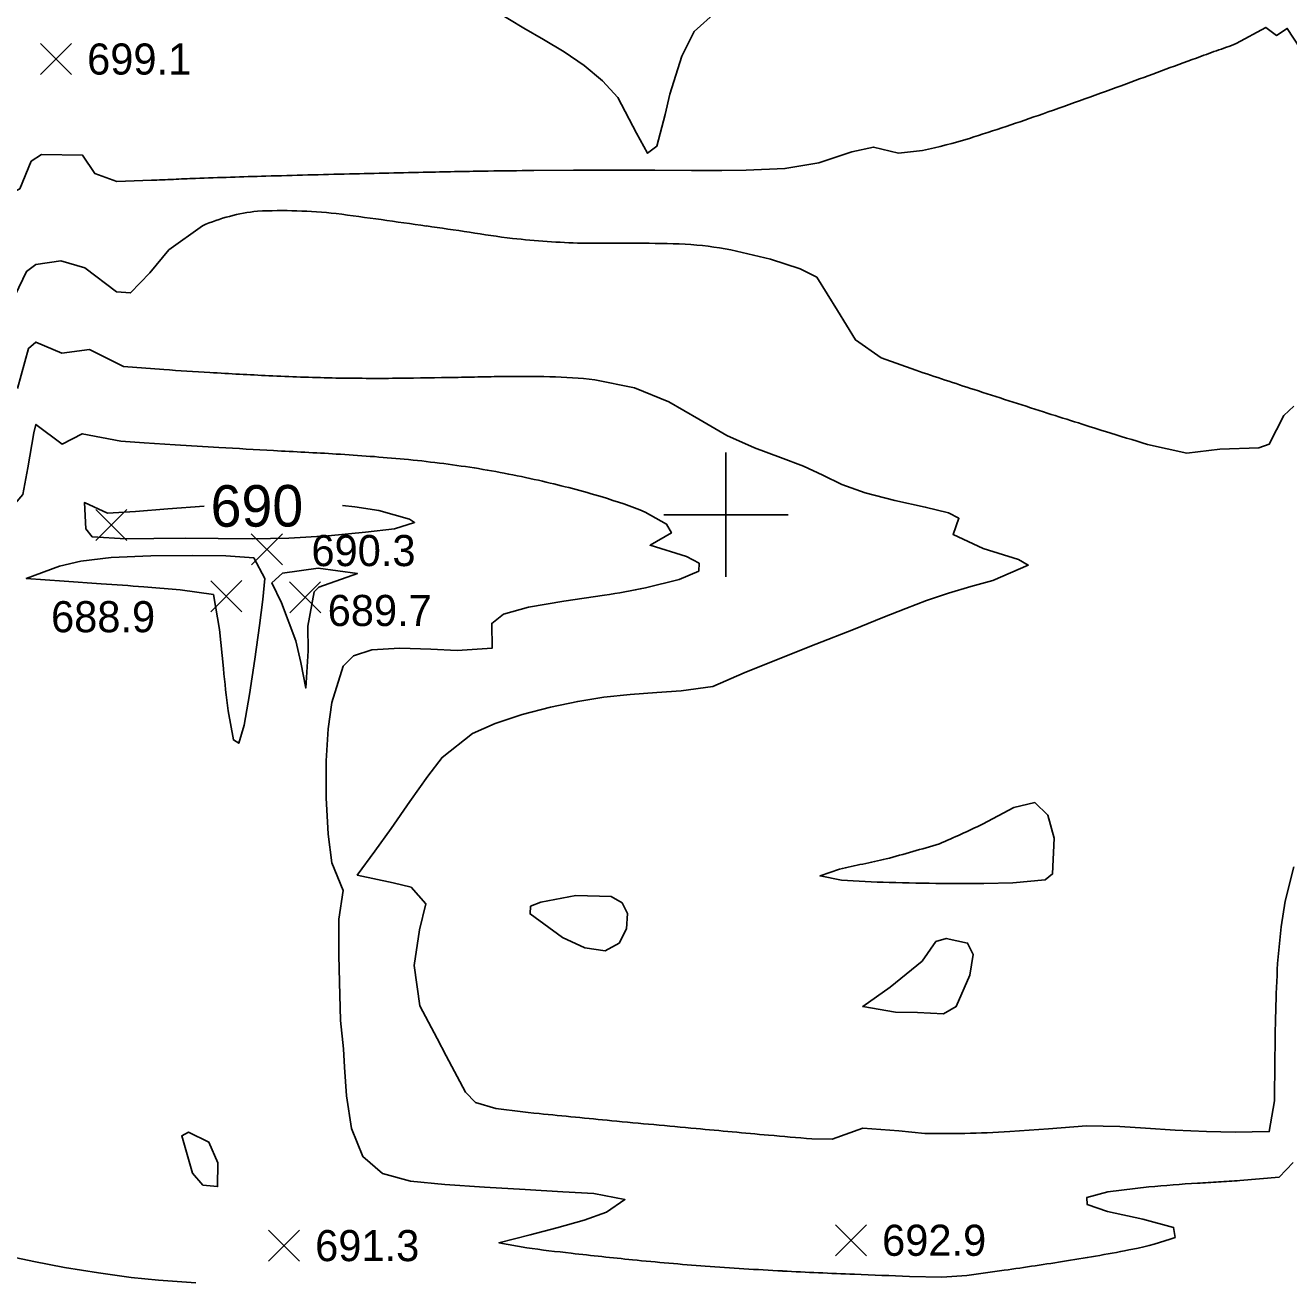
# Model space of a CAD drawing. Extents: x 2566079 to 2571326, y 424054 to 426896.
# Drawn here: x 2566662 to 2567271, y 425631 to 426236 of the extents above; entities that cross this region are included whole.
import ezdxf

# ---------------------------------------------------------------- set-up
doc = ezdxf.new("R2010")
doc.units = 0
for name, color, linetype in [('Contour_ADS_Label_Major', 7, 'Continuous'), ('Contour_ADS_Major', 7, 'Continuous'), ('Contour_ADS_Minor', 7, 'Continuous'), ('Contour_ADS_Spot_Elevation', 7, 'Continuous'), ('Contour_ADS_Tick', 7, 'Continuous')]:
    doc.layers.add(name, color=color, linetype=linetype)

# ---------------------------------------------------------------- blocks, each defined once
blk = doc.blocks.new('S890')
at = {"layer": 'Contour_ADS_Tick'}
for p, q in [((0, -0.5), (0, 0.5)), ((-0.5, 0), (0.5, 0))]:
    blk.add_line(p, q, dxfattribs=at)
blk = doc.blocks.new('S750')
at = {"layer": 'Contour_ADS_Spot_Elevation'}
for p, q in [((-0.5, 0.498), (0.5, -0.498)), ((-0.498, -0.5), (0.498, 0.5))]:
    blk.add_line(p, q, dxfattribs=at)

msp = doc.modelspace()

# ---------------------------------------------------------------- linework, layer by layer
at = {"layer": 'Contour_ADS_Major'}
for points in [[(2566888.81, 426242.96), (2566902.59, 426234.55), (2566911.98, 426229.21), (2566921.97, 426223.21), (2566931.71, 426216.58), (2566940.54, 426209.24), (2566947.81, 426201.1), (2566956.85, 426183.98), (2566962.22, 426174.26), (2566966.65, 426177.67), (2566970.7, 426193), (2566973.03, 426202.77), (2566978.76, 426221.15), (2566984.63, 426233), (2566995.41, 426242.7)], [(2566815.11, 426004.41), (2566821.12, 426003.85), (2566832.73, 426001.97), (2566847.42, 425997.84), (2566849.9, 425996.21), (2566840.22, 425993.27), (2566826.27, 425991.54), (2566808.31, 425989.89), (2566789.3, 425988.76), (2566771.62, 425988.44), (2566755.23, 425988.61), (2566739.52, 425988.77), (2566724.24, 425988.59), (2566710.64, 425988.37), (2566694.44, 425989.4), (2566691.4, 425993.17), (2566690.77, 426005.9), (2566701.93, 426000.74), (2566715.39, 426001.5), (2566730.94, 426002.84), (2566748.45, 426004.19)], [(2566698.75, 425966.73), (2566680.91, 425967.98), (2566662.72, 425969.27), (2566678.81, 425975.27), (2566689.01, 425977.58), (2566703.6, 425979.38), (2566722.68, 425980.24), (2566742.64, 425980.36), (2566758.95, 425980.15), (2566772.34, 425979.25), (2566777.69, 425969.22), (2566776.72, 425959.21), (2566775.07, 425946.63), (2566772.85, 425930.39), (2566770.33, 425913.33), (2566767.76, 425898.51), (2566765.18, 425889.83), (2566762.6, 425891.45), (2566760.04, 425905.46)], [(2566752.92, 425961.49), (2566736.86, 425963.87), (2566719.31, 425965.25)], [(2566757.72, 425925.87), (2566755.84, 425944.67), (2566752.92, 425961.49), (2566752.92, 425961.49)], [(2566550.65, 425693.94), (2566568.5, 425685.76), (2566581.26, 425680.38), (2566598.08, 425674.36), (2566609.39, 425672.46), (2566620.97, 425670.92), (2566634.05, 425668.83), (2566644.64, 425666.21), (2566649.77, 425663.14), (2566650.37, 425659.79), (2566638.84, 425647.23), (2566654.95, 425642.36), (2566666.37, 425639.9), (2566681.19, 425637.14), (2566697.58, 425634.46), (2566713.29, 425632.28), (2566726.44, 425630.92), (2566744.39, 425629.75)]]:
    msp.add_lwpolyline(points, dxfattribs=at)
msp.add_lwpolyline([(2566801.49, 425962.77), (2566798.51, 425946.32), (2566798.61, 425934.46), (2566797.48, 425916.45), (2566795.05, 425928.71), (2566792.68, 425939.17), (2566785.71, 425957.59), (2566781.15, 425967.13), (2566786.17, 425971.82), (2566803.41, 425974.3), (2566822.37, 425971.65), (2566803.73, 425965.07), (2566801.49, 425962.77)], close=True, dxfattribs=at)
for centre, radius, start, end in [((2566317.5, 420526.84), 5453.23, 85.77441, 85.99099), ((2567577.21, 426008.68), 823.67, 185.77049, 187.19943)]:
    msp.add_arc(centre, radius, start, end, dxfattribs=at)
at = {"layer": 'Contour_ADS_Minor'}
msp.add_line((2567102.92, 425841.36), (2567102.92, 425841.36), dxfattribs=at)
for points in [[(2567246.02, 426227.22), (2567260.29, 426234.98), (2567265.45, 426231.12), (2567270.63, 426234.47), (2567276.99, 426224.58), (2567283.12, 426207.93), (2567287.63, 426192.52), (2567294.86, 426177.28), (2567304.09, 426161.8), (2567306.68, 426151.66), (2567308.54, 426137.36), (2567309.79, 426121.24), (2567310.64, 426106.44), (2567311.82, 426086.51), (2567313.44, 426069.32), (2567317.06, 426059.43), (2567325.67, 426049.24), (2567340.46, 426039.34), (2567357.71, 426030.67), (2567372.46, 426024.26), (2567387.1, 426019.15), (2567405.23, 426018.1), (2567416.59, 426017.44)], [(2566907.32, 426165.97), (2566926.55, 426166.06), (2566946.27, 426166.08), (2566965.8, 426166.06), (2566983.44, 426166.01), (2566997.95, 426165.99), (2567009.74, 426166.06), (2567028.46, 426166.89), (2567044.79, 426169.74), (2567060.68, 426174.91), (2567071.13, 426177.3), (2567083.13, 426174.37), (2567094.78, 426175.56)], [(2566544.25, 426028.42), (2566562.27, 426032.19), (2566577.53, 426036.32), (2566589, 426045.91), (2566601.29, 426055.53), (2566616.86, 426060.71), (2566628.65, 426064.67), (2566645.38, 426070.99), (2566648.55, 426074.11), (2566651.09, 426088.01), (2566652.22, 426106), (2566648.52, 426114.26), (2566649.21, 426128.46), (2566650.62, 426139.3), (2566652.8, 426153.69), (2566659.61, 426157.16), (2566665.06, 426170.42), (2566670.11, 426173.74), (2566689.86, 426173.34), (2566695.72, 426164.58), (2566706.43, 426160.6), (2566723.04, 426161.24)], [(2566604.39, 426011.19), (2566623.68, 426012.18), (2566637.64, 426012.92), (2566648.09, 426013.68), (2566650.57, 426031.19), (2566651.81, 426042.71), (2566653.18, 426056.72), (2566654.54, 426072.32), (2566655.76, 426087.28), (2566657.32, 426105.86), (2566662.87, 426117.32), (2566667.28, 426120.72), (2566679.3, 426122.41), (2566690.95, 426119.07), (2566706.14, 426107.46), (2566713.03, 426106.95), (2566722.27, 426116.69), (2566731.49, 426127.75), (2566747.74, 426139.36)], [(2567002.3, 426127.73), (2567021.52, 426123.3), (2567035.8, 426118.59), (2567043.77, 426114.59), (2567053.71, 426098.44), (2567062.47, 426084.29), (2567074.76, 426075.62), (2567091.54, 426069.64)], [(2566658.45, 426060.92), (2566663.73, 426080.17), (2566667.36, 426083.28), (2566679.84, 426077.96), (2566693.13, 426079.64), (2566709.63, 426071.46), (2566729.03, 426069.98)], [(2566936.8, 426065.07), (2566955.97, 426061.19), (2566972.43, 426054.42), (2566986.94, 426046.16), (2567000.48, 426038.28), (2567013.75, 426032.21), (2567026.3, 426027.53), (2567037.38, 426023.35), (2567046.72, 426019.02), (2567055.95, 426014.63), (2567067.15, 426010.49), (2567081.45, 426006.86), (2567096.07, 426003.69), (2567107.26, 426000.88), (2567112.31, 425998.35), (2567109.47, 425990.43), (2567123.99, 425983.67), (2567141.11, 425978.45), (2567145.7, 425975.73), (2567128.6, 425968.24), (2567118.11, 425965.33), (2567107.29, 425962.11), (2567096.74, 425958.63), (2567086.68, 425954.86), (2567075.56, 425950.38), (2567061.43, 425944.68), (2567043.35, 425937.54), (2567024.44, 425930.08), (2567008.87, 425923.73), (2566993.67, 425917.19), (2566978.42, 425915.07), (2566966.62, 425914.32), (2566953.8, 425913.39), (2566941.16, 425912.02), (2566928.54, 425910.03), (2566915.49, 425907.27), (2566901.84, 425903.64), (2566888.77, 425899.33), (2566877.75, 425894.6), (2566863.2, 425882.96), (2566856.3, 425873.9), (2566847.68, 425861.76), (2566838.55, 425848.77), (2566830.8, 425837.81), (2566822.28, 425826.28), (2566839.65, 425822.47), (2566848.25, 425820.46), (2566855.39, 425812.39), (2566852.3, 425799.95), (2566849.69, 425782.75), (2566852.42, 425763.15), (2566860.8, 425747.45), (2566865.17, 425739.13), (2566874.48, 425721.55), (2566879.23, 425716.6), (2566889.06, 425713.76)], [(2567203.24, 426033.94), (2567222.21, 426029.71), (2567238.13, 426031.55), (2567256.94, 426032.33), (2567261.89, 426034.09), (2567268.91, 426047.81), (2567273.81, 426052.36)], [(2566611.92, 425958.13), (2566593.92, 425960.38), (2566583.4, 425963), (2566579.74, 425965.88), (2566584.63, 425971.6), (2566600.29, 425978.54), (2566605.21, 425982.16), (2566589.41, 425992.02), (2566606.97, 425997.81), (2566624.76, 426000.85), (2566640.81, 426003.23), (2566657.32, 426005.49), (2566661.02, 426009.78), (2566663.47, 426022.69), (2566666.32, 426039.45), (2566667.36, 426043.53), (2566679.95, 426034.08), (2566689.66, 426039.06), (2566708.36, 426035.52), (2566719.59, 426034.73), (2566734.46, 426033.75)], [(2566961.05, 426001.29), (2566971.4, 425995.49), (2566973.72, 425991.26), (2566963.44, 425985.27), (2566981.02, 425979.89), (2566987.04, 425976.62), (2566986.89, 425972.8), (2566977.5, 425968.73), (2566961.16, 425964.73)], [(2566941.47, 425961.19), (2566921.86, 425958.27), (2566904.84, 425955.47), (2566892.76, 425952.06), (2566887.11, 425947.62), (2566887.23, 425935.6), (2566870.42, 425934.49), (2566857.75, 425935.25), (2566842.73, 425935.69), (2566829.3, 425934.88), (2566820.46, 425932.05), (2566815.41, 425926.96), (2566810.07, 425909.5), (2566808.29, 425896.85), (2566807.32, 425881.38), (2566807.35, 425863.52), (2566808.28, 425846), (2566809.94, 425832.17), (2566815.42, 425818.87), (2566813.37, 425804.98), (2566813.36, 425787.7), (2566813.65, 425774.71), (2566814.22, 425756.1), (2566815.61, 425742.57), (2566816.19, 425733.71), (2566817.09, 425719.82), (2566819.52, 425704.06), (2566824.95, 425690.57), (2566834.49, 425682.47), (2566847.89, 425678.66), (2566864.53, 425677.02), (2566883.58, 425675.78), (2566903.24, 425674.63), (2566921.45, 425673.61), (2566936.35, 425672.7), (2566951.27, 425669.79), (2566942.47, 425663.67), (2566931.58, 425659.92), (2566918.54, 425656.18), (2566905.69, 425652.88), (2566890.58, 425649.01), (2566903.98, 425646.51)], [(2567124.34, 425822.23), (2567138.3, 425822.56), (2567153.9, 425824.04), (2567157.47, 425826.85), (2567158.29, 425844.07), (2567155.24, 425855.09), (2567148.98, 425861.22), (2567138.77, 425858.87), (2567123.72, 425850.8)], [(2567054.79, 425829.11), (2567045.41, 425825.89), (2567055.66, 425823.85)], [(2567265.97, 425783.58), (2567267.64, 425801.26), (2567269.65, 425813.65), (2567273.7, 425830.28)], [(2567136.89, 425702.61), (2567155.52, 425703.85), (2567173.78, 425705.45), (2567189.81, 425705), (2567202.26, 425704.17), (2567216.61, 425703.31), (2567231.67, 425702.67), (2567245.53, 425702.28), (2567261.91, 425702.63), (2567264.52, 425717.38), (2567264.64, 425736.71)], [(2567041.39, 425699.14), (2567051.21, 425698.88), (2567066.04, 425704.23), (2567083.36, 425703.03), (2567095.85, 425701.73), (2567115.11, 425701.69)], [(2567247.73, 425678.97), (2567266.72, 425680.67), (2567273.47, 425687.73)], [(2567216.62, 425651.59), (2567215.8, 425656.38), (2567201.05, 425660.39), (2567183.92, 425664.01), (2567174.09, 425667.49), (2567173.97, 425670.76), (2567184.1, 425673.63), (2567203.8, 425675.95)], [(2567088.46, 425632.81), (2567104.1, 425632.47), (2567116.06, 425633.25), (2567134.12, 425635.74)]]:
    msp.add_lwpolyline(points, dxfattribs=at)
for points in [[(2566910.7, 425813.25), (2566905.85, 425811.26), (2566905.58, 425807.51), (2566921.22, 425796.1), (2566931.9, 425791.26), (2566941.77, 425789.78), (2566948.61, 425793.48), (2566952.13, 425800.42), (2566952.51, 425807.7), (2566949.95, 425812.94), (2566944.7, 425815.91), (2566927.57, 425816.36), (2566910.7, 425813.25)], [(2567092.37, 425759.96), (2567104.94, 425759.4), (2567111.03, 425762.83), (2567117.52, 425778.07), (2567119.21, 425787.98), (2567116.53, 425793.48), (2567106.24, 425795.75), (2567101.25, 425794.32), (2567094.61, 425784.83), (2567079.13, 425772.18), (2567065.95, 425762.88), (2567081.69, 425760.19), (2567092.37, 425759.96)], [(2566747.86, 425676.76), (2566754.93, 425676.11), (2566755.12, 425687.59), (2566750.74, 425697.46), (2566740.86, 425702.3), (2566737.64, 425700.58), (2566742.78, 425682.59), (2566747.86, 425676.76)]]:
    msp.add_lwpolyline(points, close=True, dxfattribs=at)
for centre, radius, start, end in [((2570842.74, 416355.71), 10506.34, 110.075097, 110.130789), ((2567198.83, 426341.74), 123.86, 287.66698, 292.39504), ((2570854.22, 416328.35), 10535.98, 110.138192, 110.236053), ((2565350.31, 431237.67), 5356.82, 290.12074, 290.31326), ((2565970.05, 429546.08), 3555.28, 289.43276, 290.12053), ((2566784.37, 427236.99), 1106.8, 287.50823, 289.44868), ((2567034.08, 426453.76), 284.74, 282.30928, 287.00276), ((2566905.85, 421611.31), 4553.73, 91.60597, 92.03385), ((2567032.9, 417243.44), 8923.45, 91.376453, 91.635431), ((2567052.5, 416687.25), 9479.95, 91.184958, 91.414142), ((2566979.07, 420267.48), 5898.96, 90.910261, 91.191011), ((2566938.5, 422736.74), 3429.37, 90.52096, 90.88788), ((2566550.58, 430170.55), 4013.02, 272.46307, 272.61456), ((2566840.62, 423818.88), 2345.27, 92.35526, 92.61446), ((2566783.6, 426057.22), 89.63, 96.0414, 113.58653), ((2566785.8, 425899.59), 247.04, 83.88866, 92.69847), ((2566330.18, 422494.07), 3682.81, 81.79729, 82.48094), ((2565864.66, 419221.83), 6988.01, 81.6757, 81.847358), ((2566958.7, 426633.41), 503.97, 260.59517, 262.97424), ((2566946.26, 426604.14), 473.49, 264.03579, 268.09031), ((2566937.17, 426573.55), 442.68, 269.13474, 270.86526), ((2566949.41, 424629.35), 1501.58, 89.70207, 90.21223), ((2566954.08, 425276.42), 854.5, 88.23421, 89.78942), ((2566965.2, 425923.2), 207.87, 79.71977, 85.80475), ((2566881.84, 428319.27), 2254.47, 266.11335, 266.67943), ((2566886.62, 428291.91), 2227.45, 266.51604, 267.24919), ((2566840.62, 427355.13), 1289.54, 267.29311, 268.64826), ((2566832.06, 427251.45), 1185.7, 268.94355, 270.34544), ((2566790.5, 430376.74), 4311.24, 270.64737, 271.0065), ((2566740.06, 433347.38), 7282.31, 270.992717, 271.092183), ((2566905.67, 424889.6), 1177.1, 90.68946, 91.30481), ((2566901.4, 425305.52), 761.16, 88.96479, 90.74436), ((2566908.85, 425815.26), 251.37, 83.61545, 88.56321), ((2568001.24, 428779.73), 2858.69, 251.44458, 252.03954), ((2568872.64, 431448.17), 5665.81, 251.97792, 252.33201), ((2568565.93, 430457.74), 4629.02, 252.22855, 252.61793), ((2567620.42, 427435.21), 1462.05, 252.59334, 253.42069), ((2567015.75, 430370.66), 4346.02, 266.28904, 266.56841), ((2567285.4, 435150.96), 9133.91, 266.674811, 266.840053), ((2567565.99, 440358.18), 14348.68, 266.867525, 266.928031), ((2566725.41, 424586.01), 1445.88, 86.55979, 87.16025), ((2566747.18, 424961.37), 1069.89, 84.75735, 86.51744), ((2566788.06, 425435.81), 593.71, 81.21793, 84.50281), ((2566801.35, 425539.33), 489.38, 76.97871, 80.90423), ((2566822.25, 425619.47), 406.6, 73.12379, 77.30454), ((2566880.47, 425804.46), 212.69, 67.73607, 73.66417), ((2566867.83, 426427.34), 471.93, 278.97762, 281.40664), ((2566863.45, 426396.65), 604.72, 293.32857, 295.49291), ((2566864.18, 426632.1), 825.99, 284.94897, 286.80027), ((2566982.58, 426236.06), 413, 281.65538, 283.25093), ((2567091.47, 425689.11), 144.72, 100.12775, 104.68125), ((2567089.26, 426269.3), 446.71, 265.68664, 268.64317), ((2567110.16, 426840.38), 1018.16, 268.22827, 269.67142), ((2567114.82, 426811.14), 988.96, 269.39144, 270.55133), ((2567927.7, 425745), 662.85, 176.66356, 178.65167), ((2568829.52, 425723.11), 1564.94, 178.62734, 179.50213), ((2566984.19, 426425.6), 718.17, 262.38769, 264.06528), ((2567452.62, 431084.25), 5400.31, 264.23255, 264.60566), ((2568107.1, 437923.5), 12270.8, 264.565422, 264.756103), ((2567862.54, 435153.81), 9490.36, 264.698097, 264.910092), ((2567204.91, 427781.16), 2088.44, 264.9361, 265.50929), ((2567098.45, 426354.36), 652.88, 271.46218, 273.37536), ((2567294.27, 424630.53), 1049.33, 93.65764, 94.94609), ((2567330.13, 424096.15), 1584.9, 93.34965, 93.71909), ((2567199.75, 426384.04), 706.71, 273.06416, 273.89265), ((2567168.59, 425784.65), 141.46, 281.25725, 289.84599), ((2567053.99, 426810.31), 1173.43, 262.65507, 263.70793), ((2567049.44, 426384.24), 752.78, 278.76271, 281.24306), ((2567138.39, 427486.63), 1854.95, 263.40641, 264.32566), ((2567108.44, 427200.97), 1567.73, 264.38258, 265.66806), ((2566909.18, 427234.04), 1614.05, 278.01098, 279.0879), ((2567124.23, 427478.17), 1845.33, 265.82926, 266.98937), ((2567168.64, 428317.5), 2685.84, 266.98358, 267.72269), ((2567158.78, 427920.42), 2288.69, 267.57442, 268.23928)]:
    msp.add_arc(centre, radius, start, end, dxfattribs=at)

# ---------------------------------------------------------------- block references
at = {"layer": 'Contour_ADS_Spot_Elevation', "xscale": 15, "yscale": 15}
for p in [(2566677.05, 426219.72), (2566703.74, 425995.1), (2566778.69, 425983.32), (2566759.14, 425960.72), (2566797.16, 425960.16), (2567060.29, 425650.2), (2566786.98, 425647.63)]:
    msp.add_blockref('S750', p, dxfattribs=at)
at = {"layer": 'Contour_ADS_Tick', "xscale": 60, "yscale": 60}
msp.add_blockref('S890', (2567000, 426000), dxfattribs=at)

# ---------------------------------------------------------------- texts
at = {"layer": 'Contour_ADS_Label_Major'}
msp.add_text('690', height=20, rotation=0.19164, dxfattribs=at).set_placement((2566751.61, 425994.2))
at = {"layer": 'Contour_ADS_Spot_Elevation'}
for s, p in [('699.1', (2566692.05, 426212.22)), ('690.3', (2566800.18, 425975.23)), ('689.7', (2566808.02, 425946.35)), ('688.9', (2566674.65, 425943.35)), ('692.9', (2567075.29, 425642.7)), ('691.3', (2566801.98, 425640.13))]:
    msp.add_text(s, height=15, dxfattribs=at).set_placement(p)

doc.saveas('drawing.dxf')
